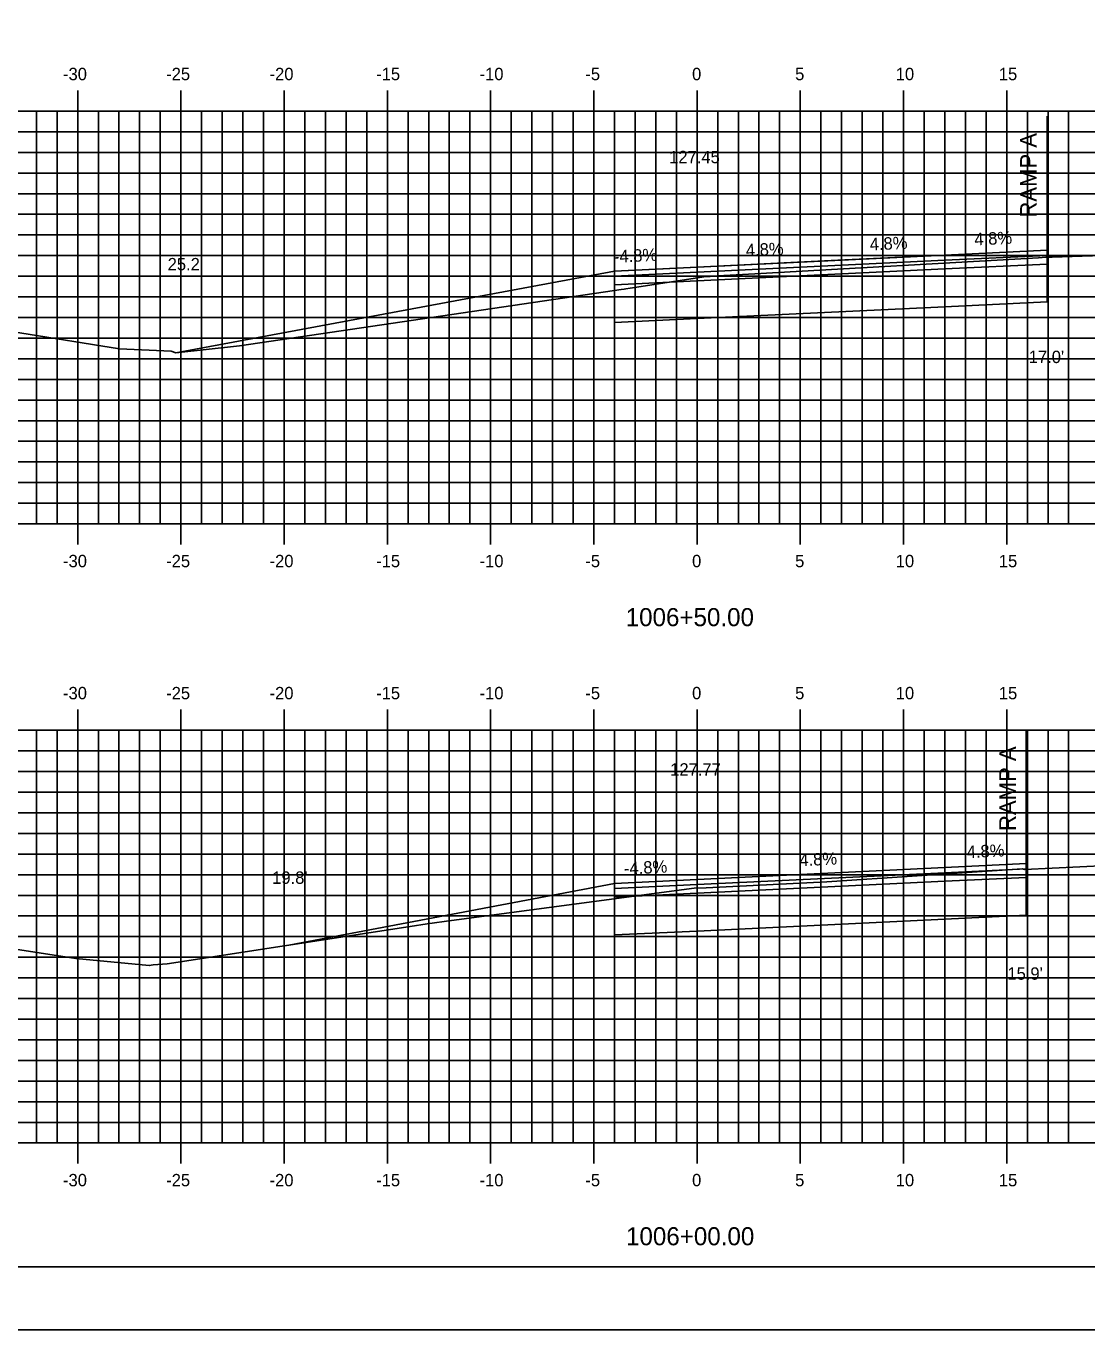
# Model space of a CAD drawing. Extents: x 851517 to 851688, y 365624 to 365734.
# Drawn here: x 851567.3 to 851618.7, y 365624 to 365687.1 of the extents above; entities that cross this region are included whole.
import ezdxf

# ---------------------------------------------------------------- set-up
doc = ezdxf.new("R2010")
doc.units = 0
for name, color, linetype in [('ANNOTATION', 7, 'Continuous'), ('BORDER', 7, 'Continuous'), ('D_Roadway_Centerline', 7, 'Continuous'), ('D_Roadway_Centerline_Text', 7, 'Continuous'), ('D_Roadway_Edge_Shoulder', 7, 'Continuous'), ('D_Roadway_Edge_TW', 7, 'Continuous'), ('D_Roadway_FinishedGrade', 7, 'Continuous'), ('D_Roadway_Pavement', 7, 'Continuous'), ('D_Roadway_SubGrade', 7, 'Continuous'), ('D_Text_Standard', 7, 'Continuous'), ('H_V ANNOTATION', 7, 'Continuous'), ('M_Roadway_Centerline', 7, 'Continuous'), ('MAJOR', 7, 'Continuous'), ('MINOR', 7, 'Continuous'), ('PLOT BOUNDARY', 7, 'Continuous'), ('S_Roadway_Centerline', 7, 'Continuous')]:
    doc.layers.add(name, color=color, linetype=linetype)

msp = doc.modelspace()

# ---------------------------------------------------------------- linework, layer by layer
at = {"layer": 'BORDER'}
msp.add_lwpolyline([(851524.766, 365627.027), (851684.766, 365627.027), (851684.766, 365732.027), (851524.766, 365732.027)], close=True, dxfattribs=at)
at = {"layer": 'D_Roadway_Centerline'}
for p, q in [((851595.766, 365675.28), (851574.517, 365671.312)), ((851595.766, 365645.605), (851579.989, 365642.612))]:
    msp.add_line(p, q, dxfattribs=at)
msp.add_lwpolyline([(851595.766, 365675.28), (851598.121, 365675.393), (851599.764, 365675.472), (851599.765, 365675.472), (851606.586, 365675.799), (851611.763, 365676.048), (851611.765, 365676.048), (851616.721, 365676.286), (851616.722, 365676.286)], dxfattribs=at)
at = {"layer": 'D_Roadway_Edge_Shoulder'}
for points in [[(851599.765, 365675.472), (851595.766, 365675.28), (851595.766, 365675.03), (851599.765, 365675.222)], [(851599.766, 365645.797), (851595.766, 365645.605), (851595.766, 365645.355), (851599.766, 365645.547)]]:
    msp.add_lwpolyline(points, close=True, dxfattribs=at)
at = {"layer": 'D_Roadway_Edge_TW'}
for points in [[(851599.765, 365675.472), (851611.765, 365676.048), (851611.765, 365675.798), (851599.765, 365675.222)], [(851611.765, 365676.048), (851616.722, 365676.286), (851616.722, 365676.036), (851611.765, 365675.798)], [(851599.766, 365645.797), (851611.765, 365646.373), (851611.765, 365646.123), (851599.766, 365645.547)], [(851611.765, 365646.373), (851615.715, 365646.563), (851615.715, 365646.313), (851611.765, 365646.123)]]:
    msp.add_lwpolyline(points, close=True, dxfattribs=at)
at = {"layer": 'D_Roadway_FinishedGrade'}
for p, q in [((851611.765, 365676.048), (851611.765, 365675.798)), ((851611.765, 365676.048), (851611.765, 365675.798)), ((851611.765, 365676.048), (851611.765, 365675.798)), ((851616.722, 365676.286), (851616.722, 365676.036)), ((851616.722, 365676.286), (851616.722, 365676.036)), ((851616.722, 365676.286), (851616.722, 365676.036)), ((851595.766, 365675.28), (851595.766, 365675.03)), ((851595.766, 365675.28), (851595.766, 365675.03)), ((851595.766, 365675.28), (851595.766, 365675.03)), ((851599.765, 365675.472), (851599.765, 365675.222)), ((851599.765, 365675.472), (851599.765, 365675.222)), ((851599.765, 365675.472), (851599.765, 365675.222)), ((851611.765, 365646.373), (851611.765, 365646.123)), ((851611.765, 365646.373), (851611.765, 365646.123)), ((851611.765, 365646.373), (851611.765, 365646.123)), ((851615.715, 365646.563), (851615.715, 365646.313)), ((851615.715, 365646.563), (851615.715, 365646.313)), ((851615.715, 365646.563), (851615.715, 365646.313)), ((851595.766, 365645.605), (851595.766, 365645.355)), ((851595.766, 365645.605), (851595.766, 365645.355)), ((851595.766, 365645.605), (851595.766, 365645.355)), ((851599.766, 365645.797), (851599.766, 365645.547)), ((851599.766, 365645.797), (851599.766, 365645.547)), ((851599.766, 365645.797), (851599.766, 365645.547))]:
    msp.add_line(p, q, dxfattribs=at)
at = {"layer": 'D_Roadway_Pavement'}
for points in [[(851611.765, 365675.798), (851616.722, 365676.036), (851616.722, 365675.62), (851611.765, 365675.382)], [(851599.765, 365675.222), (851595.766, 365675.03), (851595.766, 365674.614), (851599.765, 365674.806)], [(851599.765, 365675.222), (851611.765, 365675.798), (851611.765, 365675.382), (851599.765, 365674.806)], [(851611.765, 365646.123), (851615.715, 365646.313), (851615.715, 365645.896), (851611.765, 365645.707)], [(851599.766, 365645.547), (851595.766, 365645.355), (851595.766, 365644.939), (851599.766, 365645.131)], [(851599.766, 365645.547), (851611.765, 365646.123), (851611.765, 365645.707), (851599.766, 365645.131)]]:
    msp.add_lwpolyline(points, close=True, dxfattribs=at)
at = {"layer": 'D_Roadway_SubGrade'}
for p, q in [((851616.722, 365682.783), (851616.722, 365673.786)), ((851615.715, 365653.06), (851615.715, 365644.063))]:
    msp.add_line(p, q, dxfattribs=at)
for points in [[(851599.765, 365674.806), (851595.766, 365674.614), (851595.766, 365675.114), (851595.766, 365675.28), (851595.766, 365672.78), (851599.765, 365672.972)], [(851599.765, 365674.806), (851611.765, 365675.382), (851611.765, 365673.548), (851599.765, 365672.972)], [(851611.765, 365675.382), (851616.722, 365675.62), (851616.722, 365673.786), (851611.765, 365673.548)], [(851599.766, 365645.131), (851595.766, 365644.939), (851595.766, 365645.439), (851595.766, 365645.605), (851595.766, 365643.105), (851599.766, 365643.297)], [(851599.766, 365645.131), (851611.765, 365645.707), (851611.765, 365643.873), (851599.766, 365643.297)], [(851611.765, 365645.707), (851615.715, 365645.896), (851615.715, 365644.063), (851611.765, 365643.873)]]:
    msp.add_lwpolyline(points, close=True, dxfattribs=at)
at = {"layer": 'MAJOR'}
for p, q in [((851569.766, 365684.029), (851569.766, 365683.027)), ((851574.766, 365684.029), (851574.766, 365683.027)), ((851579.766, 365684.029), (851579.766, 365683.027)), ((851584.766, 365684.029), (851584.766, 365683.027)), ((851589.766, 365684.029), (851589.766, 365683.027)), ((851594.766, 365684.029), (851594.766, 365683.027)), ((851599.766, 365684.029), (851599.766, 365683.027)), ((851604.766, 365684.029), (851604.766, 365683.027)), ((851609.766, 365684.029), (851609.766, 365683.027)), ((851614.766, 365684.029), (851614.766, 365683.027)), ((851529.766, 365683.027), (851669.766, 365683.027)), ((851529.766, 365683.027), (851669.766, 365683.027)), ((851569.766, 365663.027), (851569.766, 365683.027)), ((851574.766, 365663.027), (851574.766, 365683.027)), ((851579.766, 365663.027), (851579.766, 365683.027)), ((851584.766, 365663.027), (851584.766, 365683.027)), ((851589.766, 365663.027), (851589.766, 365683.027)), ((851594.766, 365663.027), (851594.766, 365683.027)), ((851599.766, 365663.027), (851599.766, 365683.027)), ((851604.766, 365663.027), (851604.766, 365683.027)), ((851609.766, 365663.027), (851609.766, 365683.027)), ((851614.766, 365663.027), (851614.766, 365683.027)), ((851529.766, 365678.027), (851669.766, 365678.027)), ((851529.766, 365673.027), (851669.766, 365673.027)), ((851529.766, 365668.027), (851669.766, 365668.027)), ((851529.766, 365663.027), (851669.766, 365663.027)), ((851529.766, 365663.027), (851669.766, 365663.027)), ((851569.766, 365662.025), (851569.766, 365663.027)), ((851574.766, 365662.025), (851574.766, 365663.027)), ((851579.766, 365662.025), (851579.766, 365663.027)), ((851584.766, 365662.025), (851584.766, 365663.027)), ((851589.766, 365662.025), (851589.766, 365663.027)), ((851594.766, 365662.025), (851594.766, 365663.027)), ((851599.766, 365662.025), (851599.766, 365663.027)), ((851604.766, 365662.025), (851604.766, 365663.027)), ((851609.766, 365662.025), (851609.766, 365663.027)), ((851614.766, 365662.025), (851614.766, 365663.027)), ((851569.766, 365654.029), (851569.766, 365653.027)), ((851574.766, 365654.029), (851574.766, 365653.027)), ((851579.766, 365654.029), (851579.766, 365653.027)), ((851584.766, 365654.029), (851584.766, 365653.027)), ((851589.766, 365654.029), (851589.766, 365653.027)), ((851594.766, 365654.029), (851594.766, 365653.027)), ((851599.766, 365654.029), (851599.766, 365653.027)), ((851604.766, 365654.029), (851604.766, 365653.027)), ((851609.766, 365654.029), (851609.766, 365653.027)), ((851614.766, 365654.029), (851614.766, 365653.027)), ((851529.766, 365653.027), (851669.766, 365653.027)), ((851529.766, 365653.027), (851669.766, 365653.027)), ((851569.766, 365633.027), (851569.766, 365653.027)), ((851574.766, 365633.027), (851574.766, 365653.027)), ((851579.766, 365633.027), (851579.766, 365653.027)), ((851584.766, 365633.027), (851584.766, 365653.027)), ((851589.766, 365633.027), (851589.766, 365653.027)), ((851594.766, 365633.027), (851594.766, 365653.027)), ((851599.766, 365633.027), (851599.766, 365653.027)), ((851604.766, 365633.027), (851604.766, 365653.027)), ((851609.766, 365633.027), (851609.766, 365653.027)), ((851614.766, 365633.027), (851614.766, 365653.027)), ((851529.766, 365648.027), (851669.766, 365648.027)), ((851529.766, 365643.027), (851669.766, 365643.027)), ((851529.766, 365638.027), (851669.766, 365638.027)), ((851529.766, 365633.027), (851669.766, 365633.027)), ((851529.766, 365633.027), (851669.766, 365633.027)), ((851569.766, 365632.025), (851569.766, 365633.027)), ((851574.766, 365632.025), (851574.766, 365633.027)), ((851579.766, 365632.025), (851579.766, 365633.027)), ((851584.766, 365632.025), (851584.766, 365633.027)), ((851589.766, 365632.025), (851589.766, 365633.027)), ((851594.766, 365632.025), (851594.766, 365633.027)), ((851599.766, 365632.025), (851599.766, 365633.027)), ((851604.766, 365632.025), (851604.766, 365633.027)), ((851609.766, 365632.025), (851609.766, 365633.027)), ((851614.766, 365632.025), (851614.766, 365633.027))]:
    msp.add_line(p, q, dxfattribs=at)
at = {"layer": 'MINOR'}
for p, q in [((851567.766, 365663.027), (851567.766, 365683.027)), ((851568.766, 365663.027), (851568.766, 365683.027)), ((851570.766, 365663.027), (851570.766, 365683.027)), ((851571.766, 365663.027), (851571.766, 365683.027)), ((851572.766, 365663.027), (851572.766, 365683.027)), ((851573.766, 365663.027), (851573.766, 365683.027)), ((851575.766, 365663.027), (851575.766, 365683.027)), ((851576.766, 365663.027), (851576.766, 365683.027)), ((851577.766, 365663.027), (851577.766, 365683.027)), ((851578.766, 365663.027), (851578.766, 365683.027)), ((851580.766, 365663.027), (851580.766, 365683.027)), ((851581.766, 365663.027), (851581.766, 365683.027)), ((851582.766, 365663.027), (851582.766, 365683.027)), ((851583.766, 365663.027), (851583.766, 365683.027)), ((851585.766, 365663.027), (851585.766, 365683.027)), ((851586.766, 365663.027), (851586.766, 365683.027)), ((851587.766, 365663.027), (851587.766, 365683.027)), ((851588.766, 365663.027), (851588.766, 365683.027)), ((851590.766, 365663.027), (851590.766, 365683.027)), ((851591.766, 365663.027), (851591.766, 365683.027)), ((851592.766, 365663.027), (851592.766, 365683.027)), ((851593.766, 365663.027), (851593.766, 365683.027)), ((851595.766, 365663.027), (851595.766, 365683.027)), ((851596.766, 365663.027), (851596.766, 365683.027)), ((851597.766, 365663.027), (851597.766, 365683.027)), ((851598.766, 365663.027), (851598.766, 365683.027)), ((851600.766, 365663.027), (851600.766, 365683.027)), ((851601.766, 365663.027), (851601.766, 365683.027)), ((851602.766, 365663.027), (851602.766, 365683.027)), ((851603.766, 365663.027), (851603.766, 365683.027)), ((851605.766, 365663.027), (851605.766, 365683.027)), ((851606.766, 365663.027), (851606.766, 365683.027)), ((851607.766, 365663.027), (851607.766, 365683.027)), ((851608.766, 365663.027), (851608.766, 365683.027)), ((851610.766, 365663.027), (851610.766, 365683.027)), ((851611.766, 365663.027), (851611.766, 365683.027)), ((851612.766, 365663.027), (851612.766, 365683.027)), ((851613.766, 365663.027), (851613.766, 365683.027)), ((851615.766, 365663.027), (851615.766, 365683.027)), ((851616.766, 365663.027), (851616.766, 365683.027)), ((851617.766, 365663.027), (851617.766, 365683.027)), ((851529.766, 365682.027), (851669.766, 365682.027)), ((851529.766, 365681.027), (851669.766, 365681.027)), ((851529.766, 365680.027), (851669.766, 365680.027)), ((851529.766, 365679.027), (851669.766, 365679.027)), ((851529.766, 365677.027), (851669.766, 365677.027)), ((851529.766, 365676.027), (851669.766, 365676.027)), ((851529.766, 365675.027), (851669.766, 365675.027)), ((851529.766, 365674.027), (851669.766, 365674.027)), ((851529.766, 365672.027), (851669.766, 365672.027)), ((851529.766, 365671.027), (851669.766, 365671.027)), ((851529.766, 365670.027), (851669.766, 365670.027)), ((851529.766, 365669.027), (851669.766, 365669.027)), ((851529.766, 365667.027), (851669.766, 365667.027)), ((851529.766, 365666.027), (851669.766, 365666.027)), ((851529.766, 365665.027), (851669.766, 365665.027)), ((851529.766, 365664.027), (851669.766, 365664.027)), ((851567.766, 365633.027), (851567.766, 365653.027)), ((851568.766, 365633.027), (851568.766, 365653.027)), ((851570.766, 365633.027), (851570.766, 365653.027)), ((851571.766, 365633.027), (851571.766, 365653.027)), ((851572.766, 365633.027), (851572.766, 365653.027)), ((851573.766, 365633.027), (851573.766, 365653.027)), ((851575.766, 365633.027), (851575.766, 365653.027)), ((851576.766, 365633.027), (851576.766, 365653.027)), ((851577.766, 365633.027), (851577.766, 365653.027)), ((851578.766, 365633.027), (851578.766, 365653.027)), ((851580.766, 365633.027), (851580.766, 365653.027)), ((851581.766, 365633.027), (851581.766, 365653.027)), ((851582.766, 365633.027), (851582.766, 365653.027)), ((851583.766, 365633.027), (851583.766, 365653.027)), ((851585.766, 365633.027), (851585.766, 365653.027)), ((851586.766, 365633.027), (851586.766, 365653.027)), ((851587.766, 365633.027), (851587.766, 365653.027)), ((851588.766, 365633.027), (851588.766, 365653.027)), ((851590.766, 365633.027), (851590.766, 365653.027)), ((851591.766, 365633.027), (851591.766, 365653.027)), ((851592.766, 365633.027), (851592.766, 365653.027)), ((851593.766, 365633.027), (851593.766, 365653.027)), ((851595.766, 365633.027), (851595.766, 365653.027)), ((851596.766, 365633.027), (851596.766, 365653.027)), ((851597.766, 365633.027), (851597.766, 365653.027)), ((851598.766, 365633.027), (851598.766, 365653.027)), ((851600.766, 365633.027), (851600.766, 365653.027)), ((851601.766, 365633.027), (851601.766, 365653.027)), ((851602.766, 365633.027), (851602.766, 365653.027)), ((851603.766, 365633.027), (851603.766, 365653.027)), ((851605.766, 365633.027), (851605.766, 365653.027)), ((851606.766, 365633.027), (851606.766, 365653.027)), ((851607.766, 365633.027), (851607.766, 365653.027)), ((851608.766, 365633.027), (851608.766, 365653.027)), ((851610.766, 365633.027), (851610.766, 365653.027)), ((851611.766, 365633.027), (851611.766, 365653.027)), ((851612.766, 365633.027), (851612.766, 365653.027)), ((851613.766, 365633.027), (851613.766, 365653.027)), ((851615.766, 365633.027), (851615.766, 365653.027)), ((851616.766, 365633.027), (851616.766, 365653.027)), ((851617.766, 365633.027), (851617.766, 365653.027)), ((851529.766, 365652.027), (851669.766, 365652.027)), ((851529.766, 365651.027), (851669.766, 365651.027)), ((851529.766, 365650.027), (851669.766, 365650.027)), ((851529.766, 365649.027), (851669.766, 365649.027)), ((851529.766, 365647.027), (851669.766, 365647.027)), ((851529.766, 365646.027), (851669.766, 365646.027)), ((851529.766, 365645.027), (851669.766, 365645.027)), ((851529.766, 365644.027), (851669.766, 365644.027)), ((851529.766, 365642.027), (851669.766, 365642.027)), ((851529.766, 365641.027), (851669.766, 365641.027)), ((851529.766, 365640.027), (851669.766, 365640.027)), ((851529.766, 365639.027), (851669.766, 365639.027)), ((851529.766, 365637.027), (851669.766, 365637.027)), ((851529.766, 365636.027), (851669.766, 365636.027)), ((851529.766, 365635.027), (851669.766, 365635.027)), ((851529.766, 365634.027), (851669.766, 365634.027))]:
    msp.add_line(p, q, dxfattribs=at)
at = {"layer": 'PLOT BOUNDARY'}
msp.add_lwpolyline([(851516.673, 365623.968), (851686.673, 365623.968), (851686.673, 365733.968), (851516.673, 365733.968)], close=True, dxfattribs=at)
at = {"layer": 'S_Roadway_Centerline'}
for points in [[(851562.116, 365673.068), (851571.793, 365671.502), (851574.285, 365671.396), (851574.517, 365671.312), (851577.609, 365671.654), (851595.775, 365674.333), (851596.088, 365674.377), (851596.234, 365674.399), (851596.322, 365674.412), (851596.52, 365674.442), (851600.211, 365675.007), (851600.401, 365675.022), (851600.461, 365675.03), (851602.562, 365675.144), (851616.3, 365675.922), (851616.667, 365675.946), (851616.686, 365675.946), (851616.963, 365675.958), (851619.897, 365676.055)], [(851563.919, 365642.847), (851569.683, 365641.974), (851573.231, 365641.621), (851573.421, 365641.656), (851574.101, 365641.706), (851585.877, 365643.518), (851586.688, 365643.648), (851587.875, 365643.809), (851599.619, 365645.377), (851600.204, 365645.389), (851606.057, 365645.686), (851610.43, 365645.967), (851615.511, 365646.307), (851615.634, 365646.285), (851622.334, 365646.606)]]:
    msp.add_lwpolyline(points, dxfattribs=at)

# ---------------------------------------------------------------- texts
at = {"layer": 'ANNOTATION'}
for s, height, rotation, p in [('RAMP A', 0.8, 90, (851616.215, 365677.867)), ('4.8%', 0.6, 2.74925, (851613.212, 365676.518)), ('4.8%', 0.6, 2.74807, (851602.144, 365675.987)), ('4.8%', 0.6, 2.74806, (851608.143, 365676.275)), ('-4.8%', 0.6, 2.74824, (851595.752, 365675.68)), ('RAMP A', 0.8, 90, (851615.208, 365648.144)), ('4.8%', 0.6, 2.75412, (851612.841, 365646.826)), ('4.8%', 0.6, 2.74813, (851604.734, 365646.436)), ('-4.8%', 0.6, 2.74824, (851596.241, 365646.029))]:
    msp.add_text(s, height=height, rotation=rotation, dxfattribs=at).set_placement(p)
at = {"layer": 'D_Roadway_Centerline'}
for s, p in [('C', (851599.76, 365675.472)), ('L', (851599.765, 365675.464)), ('C', (851599.76, 365645.797)), ('L', (851599.766, 365645.789))]:
    msp.add_text(s, height=0.0146, dxfattribs=at).set_placement(p)
at = {"layer": 'D_Roadway_Centerline_Text'}
for s, p in [('127.45', (851598.414, 365680.504)), ('127.77', (851598.465, 365650.829))]:
    msp.add_text(s, height=0.6, dxfattribs=at).set_placement(p)
at = {"layer": 'D_Text_Standard'}
for s, p in [("25.2'", (851574.122, 365675.313)), ("17.0'", (851615.831, 365670.819)), ("19.8'", (851579.186, 365645.584)), ("15.9'", (851614.798, 365640.937))]:
    msp.add_text(s, height=0.6, dxfattribs=at).set_placement(p)
at = {"layer": 'H_V ANNOTATION'}
for s, height, p in [('-30', 0.6, (851569.054, 365684.527)), ('-25', 0.6, (851574.051, 365684.527)), ('-20', 0.6, (851579.059, 365684.527)), ('-15', 0.6, (851584.223, 365684.527)), ('-10', 0.6, (851589.231, 365684.527)), ('-5', 0.6, (851594.356, 365684.527)), ('0', 0.6, (851599.525, 365684.527)), ('5', 0.6, (851604.517, 365684.527)), ('10', 0.6, (851609.391, 365684.527)), ('15', 0.6, (851614.383, 365684.527)), ('-30', 0.6, (851569.054, 365660.927)), ('-25', 0.6, (851574.051, 365660.927)), ('-20', 0.6, (851579.059, 365660.927)), ('-15', 0.6, (851584.223, 365660.927)), ('-10', 0.6, (851589.231, 365660.927)), ('-5', 0.6, (851594.356, 365660.927)), ('0', 0.6, (851599.525, 365660.927)), ('5', 0.6, (851604.517, 365660.927)), ('10', 0.6, (851609.391, 365660.927)), ('15', 0.6, (851614.383, 365660.927)), ('1006+50.00', 0.875, (851596.309, 365658.07)), ('-30', 0.6, (851569.054, 365654.527)), ('-25', 0.6, (851574.051, 365654.527)), ('-20', 0.6, (851579.059, 365654.527)), ('-15', 0.6, (851584.223, 365654.527)), ('-10', 0.6, (851589.231, 365654.527)), ('-5', 0.6, (851594.356, 365654.527)), ('0', 0.6, (851599.525, 365654.527)), ('5', 0.6, (851604.517, 365654.527)), ('10', 0.6, (851609.391, 365654.527)), ('15', 0.6, (851614.383, 365654.527)), ('-30', 0.6, (851569.054, 365630.927)), ('-25', 0.6, (851574.051, 365630.927)), ('-20', 0.6, (851579.059, 365630.927)), ('-15', 0.6, (851584.223, 365630.927)), ('-10', 0.6, (851589.231, 365630.927)), ('-5', 0.6, (851594.356, 365630.927)), ('0', 0.6, (851599.525, 365630.927)), ('5', 0.6, (851604.517, 365630.927)), ('10', 0.6, (851609.391, 365630.927)), ('15', 0.6, (851614.383, 365630.927)), ('1006+00.00', 0.875, (851596.325, 365628.07))]:
    msp.add_text(s, height=height, dxfattribs=at).set_placement(p)
at = {"layer": 'M_Roadway_Centerline'}
for s, p in [('C', (851616.662, 365675.946)), ('L', (851616.667, 365675.939)), ('C', (851615.506, 365646.307)), ('L', (851615.511, 365646.3))]:
    msp.add_text(s, height=0.0146, dxfattribs=at).set_placement(p)

doc.saveas('drawing.dxf')
